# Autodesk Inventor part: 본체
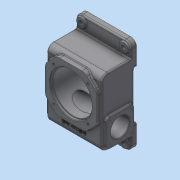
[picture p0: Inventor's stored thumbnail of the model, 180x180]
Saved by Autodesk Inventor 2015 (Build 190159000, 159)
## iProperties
Created: 2026-02
Part Number: 본체
Material: 일반
Document SubType Name: Modeling
Designer: Administrator
Density: 1 g/cm^3
Appearance: 기본값
Author: Administrator
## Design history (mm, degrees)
sketch "스케치1"
  geometry: L1 (59, -72)-(-59, -72); L2 (-59, -72)-(-59, 72); L3 (-59, 72)-(59, 72); L4 (59, 72)-(59, -72); L5 (59, -72)-(-59, 72); L6 (-59, -72)-(59, 72); 1 further point
  constraints: 12 end point, 2 midpoint, 2 parallel, 1 horizontal, 1 perpendicular
  dimensions: "d0" = 118 distance of L2.end L3.end; "d1" = 144 distance of L1.end L2.end
extrude "돌출1" new body sketch "스케치1" distance "d2" = 75; taper "d3" = 0 deg
sketch "스케치2"
  geometry: L1 (55, -42)-(-55, -42); L2 (-55, -42)-(-55, 68); L3 (-55, 68)-(55, 68); L4 (55, 68)-(55, -42); L5 (55, -42)-(-55, 68); L6 (-55, -42)-(55, 68); L7 (59, 72)-(-59, 72) reference; L8 (-59, 72)-(-59, -72) reference; L9 (0, 89)-(0, -89); 7 further points
  constraints: 14 end point, 8 midpoint, 2 parallel, 2 vertical alignment, 1 horizontal, 1 horizontal alignment, 1 perpendicular, 1 vertical
  dimensions: "d4" = 110 distance of L2.end L3.end; "d5" = 110 distance of L1.end L2.end; "d84" = 178 distance of L9.start L9.end; "d86" = 102 distance of L9.end point (0, 13)
extrude "돌출2" join sketch "스케치2" distance "d6" = 7; taper "d7" = 0 deg
chamfer "모따기1" distance "d8" = 25; stored, may be unused: second distance "d9" = 2, angle "d10" = 45 deg
fillet "모깎기1" dims "d11" = 15
fillet "모깎기2" dims "d12" = 13
sketch "스케치3"
  geometry: L1 (-59, -72)-(59, -72) reference; L2 (59, -72)-(59, 72) reference; L3 (59, 72)-(-59, 72) reference; L4 (-59, 72)-(-59, -72) reference; L5 (-59, 102)-(59, 102); L6 (59, 102)-(59, 52); L7 (59, 52)-(-59, 52); L8 (-59, 52)-(-59, 102); L9 (-59, -52)-(59, -52); L10 (59, -52)-(59, -102); L11 (59, -102)-(-59, -102); L12 (-59, -102)-(-59, -52); 1 further point
  constraints: 16 end point, 4 parallel, 3 point on line, 2 horizontal, 2 perpendicular, 1 collinear
  dimensions: "d13" = 118 distance of L5.start L5.end; "d14" = 50 distance of L7.end L5.start; "d15" = 30 distance between parallel lines of L1 L11; "d16" = 30 distance between parallel lines of L3 L5
extrude "돌출3" join sketch "스케치3" distance "d17" = 12; taper "d18" = 0 deg
sketch "스케치4"
  geometry: L1 (75, 161)-(75, -43) reference; L2 (75, 161)-(63, 161) reference; L3 (70, 111)-(75, 111); L4 (75, 111)-(75, 7); L5 (75, 7)-(70, 7); L6 (70, 7)-(70, 111); 3 further points
  constraints: 8 end point, 2 midpoint, 2 parallel, 1 horizontal, 1 horizontal alignment, 1 perpendicular, 1 point on line
  dimensions: "d19" = 5 distance between parallel lines of L1 L6; "d20" = 50 distance between parallel lines of L3 L2
extrude "돌출4" cut sketch "스케치4" stored distance "d21" = 12; taper "d22" = 0 deg
fillet "모깎기3" dims "d23" = 13
fillet "모깎기4" dims "d24" = 3
fillet "모깎기5" dims "d25" = 3
fillet "모깎기6" dims "d26" = 3
sketch "스케치5"
  geometry: L1 (23.787, 68)-(-23.787, 68) reference; L2 (-55, 36.787)-(-55, -10.787) reference; C1 r 45 at (0, 13); 3 further points
  constraints: 2 midpoint, 1 centre point, 1 coincident, 1 horizontal alignment, 1 vertical alignment
  dimensions: "d27" = 90 diameter of C1
extrude "돌출5" cut sketch "스케치5" distance "d28" = 5; taper "d29" = 0 deg
sketch "스케치6"
  geometry: C1 r 45 at (0, 0) reference; C2 r 43 at (0, 0)
  constraints: 1 centre point, 1 coincident
  dimensions: "d30" = 86 diameter of C2
extrude "돌출6" cut sketch "스케치6" distance "d31" = 61; taper "d32" = 0 deg
fillet "모깎기8" dims "d42" = 3
chamfer "모따기2" distance "d43" = 1; stored, may be unused: second distance "d44" = 2, angle "d45" = 45 deg
sketch "스케치9"
  geometry: L1 (37, -24)-(-37, -24); L2 (-37, -24)-(-37, 50); L3 (-37, 50)-(37, 50); L4 (37, 50)-(37, -24); L5 (37, -24)-(-37, 50); L6 (-37, -24)-(37, 50); C1 r 46 at (0, 13) reference; 3 further points
  constraints: 12 end point, 3 coincident, 2 midpoint, 2 parallel, 1 horizontal, 1 perpendicular
  dimensions: "d46" = 74 distance of L2.end L3.end; "d47" = 74 distance of L1.end L2.end
hole "구멍1" sketch "스케치9" at (-37, 50), (37, 50), (37, -24), (-37, -24) diameter "d48" = 4.134; stored, may be unused: countersink angle "d52" = 90 deg, drill point angle "d54" = 118 deg; dims "d49" = 10, "d50" = 4, "d51" = 2, "d53" = 12
sketch "스케치10"
  geometry: L1 (46, -89)-(-46, -89); L2 (-46, -89)-(-46, 89); L3 (-46, 89)-(46, 89); L4 (46, 89)-(46, -89); L5 (46, -89)-(-46, 89); L6 (-46, -89)-(46, 89); C1 r 9 at (-46, 89); C2 r 9 at (46, 89); C3 r 9 at (46, -89); C4 r 9 at (-46, -89); A1 r 10 centre (-46, 89) between (-46, 99) and (-56, 89) reference; 1 further point
  constraints: 12 end point, 4 centre point, 4 coincident, 2 midpoint, 2 parallel, 1 horizontal, 1 perpendicular
  dimensions: "d55" = 92 distance of L2.end L3.end (derived); "d56" = 178 distance of L1.end L2.end (derived); "d57" = 18 diameter of C1; "d58" = 18 diameter of C2; "d59" = 18 diameter of C3; "d60" = 18 diameter of C4
extrude "돌출8" join sketch "스케치10" distance "d61" = 3; taper "d62" = 0 deg
fillet "모깎기9" dims "d63" = 3
sketch "스케치11"
  geometry: L1 (46, -89)-(-46, -89); L2 (-46, -89)-(-46, 89); L3 (-46, 89)-(46, 89); L4 (46, 89)-(46, -89); L5 (46, -89)-(-46, 89); L6 (-46, -89)-(46, 89); A1 r 9 centre (-46, 89) between (-41.025, 96.5) and (-53.5, 84.025) reference; 5 further points
  constraints: 12 end point, 4 coincident, 2 midpoint, 2 parallel, 1 horizontal, 1 perpendicular
hole "구멍3" sketch "스케치11" at (-46, 89), (46, 89), (46, -89), (-46, -89) diameter "d73" = 9; stored, may be unused: countersink angle "d77" = 90 deg, drill point angle "d79" = 118 deg; dims "d74" = 10, "d75" = 4, "d76" = 2, "d78" = 12
node "작업 평면1"
sketch "스케치13"
  geometry: L1 (82.787, 74)-(82.787, 10) reference; L2 (78.787, 4.343)-(78.787, 0) reference; L3 (78.787, 0)-(69.787, 0) reference; L4 (69.787, 0)-(68.787, 1) reference; L5 (68.787, 1)-(68.787, 5) reference; L6 (68.787, 5)-(66.787, 5) reference; L7 (66.787, 5)-(66.787, 63) reference; L8 (63.787, 66)-(-16.213, 66) reference; L9 (-19.213, 63)-(-19.213, 5) reference; L10 (-19.213, 5)-(-21.213, 5) reference; L11 (-21.213, 5)-(-21.213, 1) reference; L12 (-21.213, 1)-(-22.213, 0) reference; L13 (-22.213, 0)-(-31.213, 0) reference; L14 (-31.213, 0)-(-31.213, 4.343) reference; L15 (-35.213, 10)-(-35.213, 74) reference; L16 (-32.213, 77)-(79.787, 77) reference; L17 (-7.213, 66)-(-1.213, 60); L18 (-1.213, 60)-(23.787, 60); L19 (23.787, 60)-(23.787, 66); A1 r 3 centre (79.787, 74) between (82.787, 74) and (79.787, 77) reference; A2 r 3 centre (79.787, 10) between (80.787, 7.172) and (82.787, 10) reference; A3 r 3 centre (81.787, 4.343) between (80.787, 7.172) and (78.787, 4.343) reference; A4 r 3 centre (63.787, 63) between (66.787, 63) and (63.787, 66) reference; A5 r 3 centre (-16.213, 63) between (-16.213, 66) and (-19.213, 63) reference; A6 r 3 centre (-34.213, 4.343) between (-31.213, 4.343) and (-33.213, 7.172) reference; A7 r 3 centre (-32.213, 10) between (-35.213, 10) and (-33.213, 7.172) reference; A8 r 3 centre (-32.213, 74) between (-32.213, 77) and (-35.213, 74) reference; 1 further point
  constraints: 6 end point, 1 horizontal, 1 midpoint, 1 point on line, 1 vertical alignment
  dimensions: "d87" = 45 deg angle of L19 L17; "d88" = 50 diameter of L17.end L19; "d89" = 6 distance between parallel lines of L18 L8
revolve "회전2" sketch "스케치13" stored, may be unused: angle "d90" = 90 deg
sketch "스케치14"
  geometry: C1 r 25 at (0, 0) reference; C2 r 20 at (0, 0); 1 further point
  constraints: 1 centre point, 1 coincident
  dimensions: "d91" = 40 diameter of C2
extrude "돌출9" cut sketch "스케치14" distance "d92" = 11; taper "d93" = 0 deg
fillet "모깎기10" dims "d94" = 1.5
chamfer "모따기3" distance "d95" = 1; stored, may be unused: second distance "d96" = 2, angle "d97" = 45 deg
sketch "스케치12"
  geometry: L1 (0, 0)-(0, 118) reference; L2 (72, 4)-(72, -30) reference; L3 (3, 51)-(61, 51); L4 (61, 51)-(61, -7); L5 (61, -7)-(3, -7); L6 (3, -7)-(3, 51); L7 (32, 51)-(32, -7); L8 (61, 22)-(3, 22); L9 (63, -30)-(63, -16) reference; L10 (57, -10)-(10, -10) reference; L11 (0, 0)-(0, 118) reference; L12 (57, 128)-(10, 128) reference; L13 (63, 134)-(63, 148) reference; L14 (72, 148)-(63, 148) reference; L15 (72, 148)-(72, 114) reference; L16 (70, 114)-(72, 114) reference; L17 (64, 10)-(64, 108) reference; L18 (72, 4)-(70, 4) reference; L19 (72, 4)-(72, -30) reference; L20 (72, -30)-(63, -30) reference; L21 (63, -30)-(63, -16) reference; L22 (57, -10)-(10, -10) reference; L23 (0, 0)-(0, 118) reference; L24 (57, 128)-(10, 128) reference; L25 (63, 134)-(63, 148) reference; L26 (72, 148)-(63, 148) reference; L27 (72, 148)-(72, 114) reference; L28 (70, 114)-(72, 114) reference; L29 (64, 10)-(64, 108) reference; L30 (72, 4)-(70, 4) reference; L31 (72, 4)-(72, -30) reference; L32 (72, -30)-(63, -30) reference; L33 (-10, 48.213)-(-10, 95.787) reference; L34 (-10, 72)-(0, 72); A1 r 6 centre (57, -16) between (63, -16) and (57, -10) reference; A2 r 10 centre (10, 0) between (0, 0) and (10, -10) reference; A3 r 10 centre (10, 118) between (10, 128) and (0, 118) reference; A4 r 6 centre (57, 134) between (57, 128) and (63, 134) reference; A5 r 6 centre (70, 108) between (70, 114) and (64, 108) reference; A6 r 6 centre (70, 10) between (64, 10) and (70, 4) reference; A7 r 6 centre (57, -16) between (63, -16) and (57, -10) reference; A8 r 10 centre (10, 0) between (0, 0) and (10, -10) reference; A9 r 10 centre (10, 118) between (10, 128) and (0, 118) reference; A10 r 6 centre (57, 134) between (57, 128) and (63, 134) reference; A11 r 6 centre (70, 108) between (70, 114) and (64, 108) reference; A12 r 6 centre (70, 10) between (64, 10) and (70, 4) reference; 1 further point
  constraints: 14 end point, 5 midpoint, 2 parallel, 2 perpendicular, 1 horizontal, 1 point on line
  dimensions: "d80" = 58 distance of L4.end L5.end; "d81" = 58 distance of L3.end L4.end; "d82" = 40 distance between parallel lines of L2 L7; "d98" = 50 distance between parallel lines of L8 L34
extrude "돌출10" join sketch "스케치12" distance "d99" = 5; taper "d100" = 0 deg
fillet "모깎기11" dims "d101" = 7
fillet "모깎기12" dims "d102" = 3
sketch "스케치15"
  geometry: L1 (61, 0)-(61, 44) reference; L2 (54, 51)-(10, 51) reference; C1 r 20 at (32, 22); 3 further points
  constraints: 2 midpoint, 1 centre point, 1 horizontal alignment, 1 vertical alignment
  dimensions: "d103" = 40 diameter of C1
extrude "돌출11" cut sketch "스케치15" stored distance "d104" = 5; taper "d105" = 0 deg
sketch "스케치16"
  geometry: L1 (54, 0)-(10, 0); L2 (10, 0)-(10, 44); L3 (10, 44)-(54, 44); L4 (54, 44)-(54, 0); L5 (54, 0)-(10, 44); L6 (10, 0)-(54, 44); C1 r 20 at (32, 22) reference; A1 r 7 centre (10, 44) between (10, 51) and (3, 44) reference; 5 further points
  constraints: 12 end point, 4 coincident, 2 midpoint, 2 parallel, 1 horizontal, 1 perpendicular
  dimensions: "d106" = 44 distance of L2.end L3.end (derived); "d107" = 44 distance of L1.end L2.end (derived)
hole "구멍4" sketch "스케치16" at (10, 44), (54, 44), (54, 0), (10, 0) diameter "d108" = 3.242; stored, may be unused: countersink angle "d112" = 90 deg, drill point angle "d114" = 118 deg; dims "d109" = 8, "d110" = 4, "d111" = 2, "d113" = 10
node "작업 평면2"
fillet "모깎기13" dims "d115" = 7
fillet "모깎기14" dims "d116" = 3
chamfer "모따기4" distance "d117" = 1; stored, may be unused: second distance "d118" = 2, angle "d119" = 45 deg
node "작업 평면3"
sketch "스케치17"
  geometry: L1 (-46, 13)-(0, 13); 2 further points
  constraints: 2 end point, 1 horizontal, 1 horizontal alignment, 1 vertical alignment, 2 other
  dimensions: "d121" = 65 distance of point (0, -52) L1.end
feature "엠보싱1" sketch "스케치17" dims "d122" = 0.5, "d123" = 0
fillet "모깎기15" dims "d124" = 3
sketch "스케치20"
  geometry: L1 (49, 5)-(-49, 5) reference; L2 (-52, 2)-(-52, 0) reference; L3 (-52, 0)-(-102, 0) reference; L4 (-102, 0)-(-102, 9) reference; L5 (-99, 12)-(-75, 12) reference; L6 (-72, 15)-(-72, 62) reference; L7 (-59, 75)-(-49.635, 75) reference; L8 (-49.635, 75)-(-49.635, 75.5) reference; L9 (-49.635, 75.5)-(-49.138, 75.5) reference; L10 (-49.138, 75.5)-(-49.138, 75) reference; L11 (-49.138, 75)-(-45, 75) reference; L12 (-42, 78)-(-42, 82) reference; L13 (-42, 82)-(-33, 82) reference; L14 (-33, 82)-(-32, 81) reference; L15 (-32, 81)-(-32, 77) reference; L16 (-32, 77)-(-30, 77) reference; L17 (-30, 77)-(-30, 58.735) reference; L18 (-30, 21.265)-(-30, 19) reference; L19 (-27, 16)-(-19.243, 16) reference; L20 (-17.121, 16.879)-(-12.879, 21.121) reference; L21 (-10.757, 22)-(-8, 22) reference; L22 (-8, 22)-(-7, 21) reference; L23 (-7, 21)-(-7, 12.5) reference; L24 (-5.5, 11)-(31.5, 11) reference; L25 (33, 12.5)-(33, 21) reference; L26 (33, 21)-(34, 22) reference; L27 (34, 22)-(36.757, 22) reference; L28 (38.879, 21.121)-(43.121, 16.879) reference; L29 (45.243, 16)-(53, 16) reference; L30 (56, 19)-(56, 77) reference; L31 (56, 77)-(58, 77) reference; L32 (58, 77)-(58, 81) reference; L33 (58, 81)-(59, 82) reference; L34 (59, 82)-(68, 82) reference; L35 (68, 82)-(68, 72.583) reference; L36 (72, 62)-(72, 15) reference; L37 (75, 12)-(99, 12) reference; L38 (102, 9)-(102, 0) reference; L39 (102, 0)-(52, 0) reference; L40 (52, 0)-(52, 2) reference; L41 (38, 22)-(-12, 22); A1 r 3 centre (49, 2) between (52, 2) and (49, 5) reference; A2 r 3 centre (-49, 2) between (-49, 5) and (-52, 2) reference; A3 r 3 centre (-99, 9) between (-99, 12) and (-102, 9) reference; A4 r 3 centre (-75, 15) between (-75, 12) and (-72, 15) reference; A5 r 13 centre (-59, 62) between (-59, 75) and (-72, 62) reference; A6 r 3 centre (-45, 78) between (-45, 75) and (-42, 78) reference; A7 r 20 centre (-37, 40) between (-30, 58.735) and (-30, 21.265) reference; A8 r 3 centre (-27, 19) between (-30, 19) and (-27, 16) reference; A9 r 3 centre (-19.243, 19) between (-19.243, 16) and (-17.121, 16.879) reference; A10 r 3 centre (-10.757, 19) between (-10.757, 22) and (-12.879, 21.121) reference; A11 r 1.5 centre (-5.5, 12.5) between (-7, 12.5) and (-5.5, 11) reference; A12 r 1.5 centre (31.5, 12.5) between (31.5, 11) and (33, 12.5) reference; A13 r 3 centre (36.757, 19) between (38.879, 21.121) and (36.757, 22) reference; A14 r 3 centre (45.243, 19) between (43.121, 16.879) and (45.243, 16) reference; A15 r 3 centre (53, 19) between (53, 16) and (56, 19) reference; A16 r 3 centre (71, 72.583) between (68, 72.583) and (68.75, 70.599) reference; A17 r 13 centre (59, 62) between (72, 62) and (68.75, 70.599) reference; A18 r 3 centre (75, 15) between (72, 15) and (75, 12) reference; A19 r 3 centre (99, 9) between (102, 9) and (99, 12) reference; 3 further points
  constraints: 2 end point, 2 midpoint, 1 horizontal, 1 horizontal alignment, 1 vertical alignment
  dimensions: "d127" = 50 distance of L41.start L41.end
  node "절단 모서리 투영6"
node "솔리드1"
mirror "대칭1"
node "절단 모서리 투영2"
node "절단 모서리 투영3"
node "절단 모서리 투영4"
